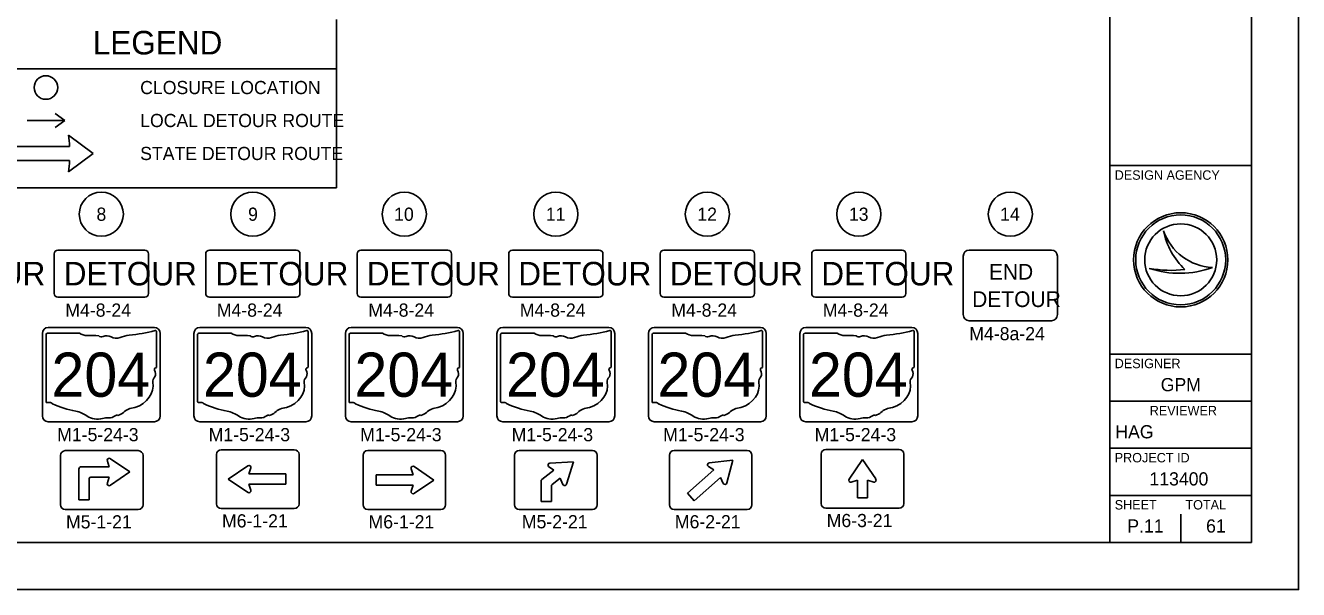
# Model space of a CAD drawing. Extents: x 1880545 to 1948545, y 79309 to 723051.
# Drawn here: x 1921540 to 1948545, y 679051 to 691027 of the extents above; entities that cross this region are included whole.
import ezdxf

# ---------------------------------------------------------------- set-up
doc = ezdxf.new("R2010")
doc.units = 0
for name, color, linetype in [('SH_Border', 7, 'Continuous'), ('SH_Cut_Line', 7, 'Continuous'), ('SH_Data', 7, 'Continuous'), ('SH_Text', 7, 'Continuous'), ('SN_P_Signs', 7, 'Continuous'), ('SN_P_Text', 7, 'Continuous'), ('UT_P_Electric', 7, 'Continuous')]:
    doc.layers.add(name, color=color, linetype=linetype)

msp = doc.modelspace()

# ---------------------------------------------------------------- linework, layer by layer
at = {"layer": 'SH_Border'}
for p, q in [((1944545, 680051), (1944545, 722051)), ((1944545, 688051), (1947545, 688051)), ((1944545, 684051), (1947545, 684051)), ((1944545, 683051), (1947545, 683051)), ((1944545, 682051), (1947545, 682051)), ((1944545, 681051), (1947545, 681051))]:
    msp.add_line(p, q, dxfattribs=at)
msp.add_lwpolyline([(1883545, 722051), (1947545, 722051), (1947545, 680051), (1883545, 680051)], close=True, dxfattribs=at)
at = {"layer": 'SH_Cut_Line'}
msp.add_lwpolyline([(1880545, 679051), (1948545, 679051), (1948545, 723051), (1880545, 723051)], close=True, dxfattribs=at)
at = {"layer": 'SH_Data'}
for p, q in [((1945679, 686670), (1945679, 686670)), ((1946045, 686051), (1946045, 686051)), ((1945379, 685870), (1945379, 685870)), ((1946719, 685888), (1946719, 685888)), ((1946045, 680051), (1946045, 680651)), ((1945295, 680401), (1945295, 680401))]:
    msp.add_line(p, q, dxfattribs=at)
for radius in [1000, 954, 954, 764]:
    msp.add_circle((1946045, 686051), radius, dxfattribs=at)
for centre, radius, start, end in [((1946776, 687046), 1160, 198.9257, 198.9319), ((1947238, 686991), 1591, 191.6379, 191.6421), ((1946776, 687046), 1160, 198.9319, 267.1657), ((1947238, 686991), 1591, 191.6421, 226.0947), ((1946023, 687791), 2026, 251.4576, 290.0832), ((1945841, 688360), 2532, 259.4964, 259.4995), ((1946023, 687791), 2026, 251.4527, 251.4576), ((1945841, 688360), 2532, 259.4995, 276.6672)]:
    msp.add_arc(centre, radius, start, end, dxfattribs=at)
at = {"layer": 'SH_Text'}
for p, q in [((1928141, 691152), (1928141, 687581)), ((1920641, 690105), (1928141, 690105)), ((1921573, 689009), (1921973, 689009)), ((1921973, 689009), (1922373, 689009)), ((1922373, 689009), (1922173, 689159)), ((1922373, 689009), (1922173, 688859)), ((1922453, 688700), (1922973, 688309)), ((1920973, 688459), (1922473, 688459)), ((1922473, 688159), (1920973, 688159)), ((1922973, 688309), (1922453, 687919)), ((1920641, 687581), (1928141, 687581))]:
    msp.add_line(p, q, dxfattribs=at)
for centre in [(1923149, 687020), (1926363, 687020), (1929576, 687020), (1932790, 687020), (1936004, 687020), (1939217, 687020), (1942431, 687020)]:
    msp.add_circle(centre, 468, dxfattribs=at)
for centre, start, end in [((1920973, 688459), 0, 9.2166), ((1920973, 688159), 350.7834, 360)]:
    msp.add_arc(centre, 1500, start, end, dxfattribs=at)
at = {"layer": 'SN_P_Signs'}
for p, q in [((1921977, 684467), (1921977, 683044)), ((1922686, 684491), (1922000, 684491)), ((1924321, 683782), (1924321, 684526)), ((1925191, 684467), (1925191, 683044)), ((1925900, 684491), (1925214, 684491)), ((1927534, 683782), (1927534, 684526)), ((1928404, 684467), (1928404, 683044)), ((1929114, 684491), (1928427, 684491)), ((1930748, 683782), (1930748, 684526)), ((1931618, 684467), (1931618, 683044)), ((1932328, 684491), (1931641, 684491)), ((1933962, 683782), (1933962, 684526)), ((1934832, 684467), (1934832, 683044)), ((1935541, 684491), (1934855, 684491)), ((1937175, 683782), (1937175, 684526)), ((1938045, 684467), (1938045, 683044)), ((1938755, 684491), (1938069, 684491)), ((1940389, 683782), (1940389, 684526)), ((1924320, 683782), (1924321, 683782)), ((1927534, 683782), (1927534, 683782)), ((1930748, 683782), (1930748, 683782)), ((1933962, 683782), (1933962, 683782)), ((1937175, 683782), (1937175, 683782)), ((1940389, 683782), (1940389, 683782))]:
    msp.add_line(p, q, dxfattribs=at)
for points in [[(1922024, 684614), (1924274, 684614)], [(1925238, 684614), (1927488, 684614)], [(1928451, 684614), (1930701, 684614)], [(1931665, 684614), (1933915, 684614)], [(1934879, 684614), (1937129, 684614)], [(1938092, 684614), (1940342, 684614)], [(1921899, 682739), (1921899, 684489)], [(1924399, 684489), (1924399, 682739)], [(1925113, 682739), (1925113, 684489)], [(1927613, 684489), (1927613, 682739)], [(1928326, 682739), (1928326, 684489)], [(1930826, 684489), (1930826, 682739)], [(1931540, 682739), (1931540, 684489)], [(1934040, 684489), (1934040, 682739)], [(1934754, 682739), (1934754, 684489)], [(1937254, 684489), (1937254, 682739)], [(1937967, 682739), (1937967, 684489)], [(1940467, 684489), (1940467, 682739)], [(1924274, 682614), (1922024, 682614)], [(1927488, 682614), (1925238, 682614)], [(1930701, 682614), (1928451, 682614)], [(1933915, 682614), (1931665, 682614)], [(1937129, 682614), (1934879, 682614)], [(1940342, 682614), (1938092, 682614)]]:
    msp.add_lwpolyline(points, dxfattribs=at)
for centre, start, end in [((1922024, 684489), 90, 180), ((1924274, 684489), 0, 90), ((1925238, 684489), 90, 180), ((1927488, 684489), 0, 90), ((1928451, 684489), 90, 180), ((1930701, 684489), 0, 90), ((1931665, 684489), 90, 180), ((1933915, 684489), 0, 90), ((1934879, 684489), 90, 180), ((1937129, 684489), 0, 90), ((1938092, 684489), 90, 180), ((1940342, 684489), 0, 90), ((1922024, 682739), 180, 270), ((1924274, 682739), 270, 0), ((1925238, 682739), 180, 270), ((1927488, 682739), 270, 0), ((1928451, 682739), 180, 270), ((1930701, 682739), 270, 0), ((1931665, 682739), 180, 270), ((1933915, 682739), 270, 0), ((1934879, 682739), 180, 270), ((1937129, 682739), 270, 0), ((1938092, 682739), 180, 270), ((1940342, 682739), 270, 0)]:
    msp.add_arc(centre, 125, start, end, dxfattribs=at)
for centre, major_axis, start_param, end_param in [((1922004, 684470), (27.2, 0), 1.712693, 3.28349), ((1922850, 684656), (263, 0), 4.042523, 4.731795), ((1922937, 683692), (945, 0), 1.404758, 1.657858), ((1923152, 684477), (76, 0), 3.836095, 5.185415), ((1923263, 684313), (158, 0), 0.950623, 2.079405), ((1923467, 684538), (190, 0), 4.081561, 5.145723), ((1923803, 684056), (500, 0), 1.699011, 2.107814), ((1923486, 686431), (2485, 0), 4.814394, 5.042369), ((1924295, 684529), (26.1, 0), 6.141152, 7.989035), ((1925218, 684470), (27.2, 0), 1.712693, 3.28349), ((1926064, 684656), (263, 0), 4.042523, 4.731795), ((1926151, 683692), (945, 0), 1.404758, 1.657858), ((1926366, 684477), (76, 0), 3.836095, 5.185415), ((1926477, 684313), (158, 0), 0.950623, 2.079405), ((1926681, 684538), (190, 0), 4.081561, 5.145723), ((1927017, 684056), (500, 0), 1.699011, 2.107814), ((1926700, 686431), (2485, 0), 4.814394, 5.042369), ((1927508, 684529), (26.1, 0), 6.141152, 7.989035), ((1928431, 684470), (27.2, 0), 1.712693, 3.28349), ((1929277, 684656), (263, 0), 4.042523, 4.731795), ((1929365, 683692), (945, 0), 1.404758, 1.657858), ((1929579, 684477), (76, 0), 3.836095, 5.185415), ((1929691, 684313), (158, 0), 0.950623, 2.079405), ((1929895, 684538), (190, 0), 4.081561, 5.145723), ((1930230, 684056), (500, 0), 1.699011, 2.107814), ((1929913, 686431), (2485, 0), 4.814394, 5.042369), ((1930722, 684529), (26.1, 0), 6.141152, 7.989035), ((1931645, 684470), (27.2, 0), 1.712693, 3.28349), ((1932491, 684656), (263, 0), 4.042523, 4.731795), ((1932578, 683692), (945, 0), 1.404758, 1.657858), ((1932793, 684477), (76, 0), 3.836095, 5.185415), ((1932904, 684313), (158, 0), 0.950623, 2.079405), ((1933108, 684538), (190, 0), 4.081561, 5.145723), ((1933444, 684056), (500, 0), 1.699011, 2.107814), ((1933127, 686431), (2485, 0), 4.814394, 5.042369), ((1933936, 684529), (26.1, 0), 6.141152, 7.989035), ((1934859, 684470), (27.2, 0), 1.712693, 3.28349), ((1935705, 684656), (263, 0), 4.042523, 4.731795), ((1935792, 683692), (945, 0), 1.404758, 1.657858), ((1936007, 684477), (76, 0), 3.836095, 5.185415), ((1936118, 684313), (158, 0), 0.950623, 2.079405), ((1936322, 684538), (190, 0), 4.081561, 5.145723), ((1936658, 684056), (500, 0), 1.699011, 2.107814), ((1936341, 686431), (2485, 0), 4.814394, 5.042369), ((1937149, 684529), (26.1, 0), 6.141152, 7.989035), ((1938072, 684470), (27.2, 0), 1.712693, 3.28349), ((1938918, 684656), (263, 0), 4.042523, 4.731795), ((1939006, 683692), (945, 0), 1.404758, 1.657858), ((1939220, 684477), (76, 0), 3.836095, 5.185415), ((1939332, 684313), (158, 0), 0.950623, 2.079405), ((1939536, 684538), (190, 0), 4.081561, 5.145723), ((1939871, 684056), (500, 0), 1.699011, 2.107814), ((1939554, 686431), (2485, 0), 4.814394, 5.042369), ((1940363, 684529), (26.1, 0), 6.141152, 7.989035), ((1924293, 683779), (27.9, 0), 5.05454, 6.418171), ((1927507, 683779), (27.9, 0), 5.05454, 6.418171), ((1930720, 683779), (27.9, 0), 5.05454, 6.418171), ((1933934, 683779), (27.9, 0), 5.05454, 6.418171), ((1937148, 683779), (27.9, 0), 5.05454, 6.418171), ((1940361, 683779), (27.9, 0), 5.05454, 6.418171), ((1924414, 683470), (176, 0), 2.387724, 3.262537), ((1924315, 683727), (40.4, 0), 1.883978, 3.671073), ((1924058, 683633), (242, 0), 5.934695, 6.695948), ((1927628, 683470), (176, 0), 2.387724, 3.262537), ((1927528, 683727), (40.4, 0), 1.883978, 3.671073), ((1927271, 683633), (242, 0), 5.934695, 6.695948), ((1930842, 683470), (176, 0), 2.387724, 3.262537), ((1930742, 683727), (40.4, 0), 1.883978, 3.671073), ((1930485, 683633), (242, 0), 5.934695, 6.695948), ((1934055, 683470), (176, 0), 2.387724, 3.262537), ((1933956, 683727), (40.4, 0), 1.883978, 3.671073), ((1933699, 683633), (242, 0), 5.934695, 6.695948), ((1937269, 683470), (176, 0), 2.387724, 3.262537), ((1937169, 683727), (40.4, 0), 1.883978, 3.671073), ((1936913, 683633), (242, 0), 5.934695, 6.695948), ((1940483, 683470), (176, 0), 2.387724, 3.262537), ((1940383, 683727), (40.4, 0), 1.883978, 3.671073), ((1940126, 683633), (242, 0), 5.934695, 6.695948), ((1923625, 683376), (622, 0), 5.101752, 6.440018), ((1926839, 683376), (622, 0), 5.101752, 6.440018), ((1930052, 683376), (622, 0), 5.101752, 6.440018), ((1933266, 683376), (622, 0), 5.101752, 6.440018), ((1936480, 683376), (622, 0), 5.101752, 6.440018), ((1939694, 683376), (622, 0), 5.101752, 6.440018), ((1922004, 683040), (27.4, 0), 3.00124, 4.508301), ((1922008, 683186), (209, 0), 4.665946, 4.897461), ((1922051, 682961), (75.4, 0), 0.519207, 1.627899), ((1923003, 684240), (1795, 0), 4.195997, 4.488961), ((1925218, 683040), (27.4, 0), 3.00124, 4.508301), ((1925222, 683186), (209, 0), 4.665946, 4.897461), ((1925265, 682961), (75.4, 0), 0.519207, 1.627899), ((1926216, 684240), (1795, 0), 4.195997, 4.488961), ((1928431, 683040), (27.4, 0), 3.00124, 4.508301), ((1928436, 683186), (209, 0), 4.665946, 4.897461), ((1928478, 682961), (75.4, 0), 0.519207, 1.627899), ((1929430, 684240), (1795, 0), 4.195997, 4.488961), ((1931645, 683040), (27.4, 0), 3.00124, 4.508301), ((1931649, 683186), (209, 0), 4.665946, 4.897461), ((1931692, 682961), (75.4, 0), 0.519207, 1.627899), ((1932644, 684240), (1795, 0), 4.195997, 4.488961), ((1934859, 683040), (27.4, 0), 3.00124, 4.508301), ((1934863, 683186), (209, 0), 4.665946, 4.897461), ((1934906, 682961), (75.4, 0), 0.519207, 1.627899), ((1935857, 684240), (1795, 0), 4.195997, 4.488961), ((1938073, 683040), (27.4, 0), 3.00124, 4.508301), ((1938077, 683186), (209, 0), 4.665946, 4.897461), ((1938119, 682961), (75.4, 0), 0.519207, 1.627899), ((1939071, 684240), (1795, 0), 4.195997, 4.488961), ((1922468, 682404), (562, 0), 0.823519, 1.323587), ((1923075, 682954), (356, 0), 4.026481, 4.996735), ((1923281, 682462), (293, 0), 1.495662, 1.94098), ((1923307, 682848), (190, 0), 4.691044, 5.507374), ((1923479, 682710), (53.5, 0), 1.147584, 2.315152), ((1923456, 682906), (201, 0), 4.937069, 5.64225), ((1923887, 682644), (340, 0), 1.647645, 2.488434), ((1925681, 682404), (562, 0), 0.823519, 1.323587), ((1926289, 682954), (356, 0), 4.026481, 4.996735), ((1926495, 682462), (293, 0), 1.495662, 1.94098), ((1926521, 682848), (190, 0), 4.691044, 5.507374), ((1926692, 682710), (53.5, 0), 1.147584, 2.315152), ((1926670, 682906), (201, 0), 4.937069, 5.64225), ((1927101, 682644), (340, 0), 1.647645, 2.488434), ((1928895, 682404), (562, 0), 0.823519, 1.323587), ((1929502, 682954), (356, 0), 4.026481, 4.996735), ((1929708, 682462), (293, 0), 1.495662, 1.94098), ((1929734, 682848), (190, 0), 4.691044, 5.507374), ((1929906, 682710), (53.5, 0), 1.147584, 2.315152), ((1929883, 682906), (201, 0), 4.937069, 5.64225), ((1930315, 682644), (340, 0), 1.647645, 2.488434), ((1932109, 682404), (562, 0), 0.823519, 1.323587), ((1932716, 682954), (356, 0), 4.026481, 4.996735), ((1932922, 682462), (293, 0), 1.495662, 1.94098), ((1932948, 682848), (190, 0), 4.691044, 5.507374), ((1933120, 682710), (53.5, 0), 1.147584, 2.315152), ((1933097, 682906), (201, 0), 4.937069, 5.64225), ((1933528, 682644), (340, 0), 1.647645, 2.488434), ((1935322, 682404), (562, 0), 0.823519, 1.323587), ((1935930, 682954), (356, 0), 4.026481, 4.996735), ((1936136, 682462), (293, 0), 1.495662, 1.94098), ((1936162, 682848), (190, 0), 4.691044, 5.507374), ((1936333, 682710), (53.5, 0), 1.147584, 2.315152), ((1936311, 682906), (201, 0), 4.937069, 5.64225), ((1936742, 682644), (340, 0), 1.647645, 2.488434), ((1938536, 682404), (562, 0), 0.823519, 1.323587), ((1939143, 682954), (356, 0), 4.026481, 4.996735), ((1939349, 682462), (293, 0), 1.495662, 1.94098), ((1939375, 682848), (190, 0), 4.691044, 5.507374), ((1939547, 682710), (53.5, 0), 1.147584, 2.315152), ((1939524, 682906), (201, 0), 4.937069, 5.64225), ((1939956, 682644), (340, 0), 1.647645, 2.488434)]:
    msp.add_ellipse(centre, major_axis=major_axis, ratio=0.8, start_param=start_param, end_param=end_param, dxfattribs=at)
at = {"layer": 'UT_P_Electric'}
for p, q in [((1922284, 681901), (1922284, 680851)), ((1923934, 682001), (1922384, 682001)), ((1924034, 680851), (1924034, 681901)), ((1925593, 681921), (1925593, 680871)), ((1927243, 682021), (1925693, 682021)), ((1927243, 682021), (1927243, 682021)), ((1927343, 680871), (1927343, 681921)), ((1928700, 680852), (1928700, 681902)), ((1928800, 682002), (1930350, 682002)), ((1930450, 681902), (1930450, 680852)), ((1931915, 681902), (1931915, 680852)), ((1933565, 682002), (1932015, 682002)), ((1933665, 680852), (1933665, 681902)), ((1935199, 680852), (1935199, 681902)), ((1935299, 682002), (1936849, 682002)), ((1936949, 681902), (1936949, 680852)), ((1938420, 680878), (1938420, 681928)), ((1938520, 682028), (1940070, 682028)), ((1940170, 681928), (1940170, 680878)), ((1922675, 680954), (1922675, 681610)), ((1922721, 681657), (1923315, 681657)), ((1922721, 681657), (1922721, 681657)), ((1923315, 681657), (1923274, 681797)), ((1923345, 681827), (1923753, 681547)), ((1925843, 681396), (1926257, 681681)), ((1926320, 681634), (1926281, 681506)), ((1929723, 681614), (1929763, 681486)), ((1930200, 681377), (1929787, 681661)), ((1932748, 681588), (1932637, 681664)), ((1932664, 681735), (1933165, 681766)), ((1932664, 681735), (1932664, 681735)), ((1933165, 681766), (1933014, 681287)), ((1936142, 681593), (1936027, 681663)), ((1936044, 681740), (1936543, 681799)), ((1936044, 681740), (1936044, 681740)), ((1936543, 681799), (1936420, 681320)), ((1939011, 681395), (1939295, 681809)), ((1939295, 681809), (1939575, 681401)), ((1922893, 681407), (1922893, 680954)), ((1923315, 681438), (1922925, 681438)), ((1923274, 681297), (1923315, 681438)), ((1923753, 681547), (1923345, 681268)), ((1926251, 681117), (1925843, 681396)), ((1926281, 681506), (1927062, 681506)), ((1927062, 681506), (1927062, 681287)), ((1929763, 681486), (1928982, 681486)), ((1928982, 681486), (1928982, 681267)), ((1929792, 681097), (1930200, 681377)), ((1932478, 680924), (1932478, 681354)), ((1932496, 681391), (1932748, 681588)), ((1932883, 681416), (1932709, 681279)), ((1932933, 681299), (1932883, 681416)), ((1935580, 681100), (1936142, 681593)), ((1936286, 681429), (1935724, 680936)), ((1936341, 681306), (1936286, 681428)), ((1939186, 681372), (1939057, 681332)), ((1939186, 680997), (1939186, 681372)), ((1939533, 681332), (1939404, 681372)), ((1939404, 681372), (1939404, 680997)), ((1927062, 681287), (1926281, 681287)), ((1926281, 681287), (1926320, 681159)), ((1928982, 681267), (1929763, 681267)), ((1929763, 681267), (1929723, 681139)), ((1932696, 681254), (1932696, 680924)), ((1935724, 680936), (1935580, 681100)), ((1922893, 680954), (1922675, 680954)), ((1932696, 680924), (1932478, 680924)), ((1939404, 680997), (1939186, 680997)), ((1922384, 680751), (1923934, 680751)), ((1925693, 680771), (1927243, 680771)), ((1930350, 680752), (1928800, 680752)), ((1932015, 680752), (1933565, 680752)), ((1936849, 680752), (1935299, 680752)), ((1940070, 680778), (1938520, 680778))]:
    msp.add_line(p, q, dxfattribs=at)
for points in [[(1924069, 686258), (1922229, 686258)], [(1927283, 686258), (1925443, 686258)], [(1930496, 686258), (1928656, 686258)], [(1933710, 686258), (1931870, 686258)], [(1936924, 686258), (1935084, 686258)], [(1940137, 686258), (1938297, 686258)], [(1943301, 686258), (1941561, 686258)], [(1922149, 686178), (1922149, 685338)], [(1924149, 685338), (1924149, 686178)], [(1925363, 686178), (1925363, 685338)], [(1927363, 685338), (1927363, 686178)], [(1928576, 686178), (1928576, 685338)], [(1930576, 685338), (1930576, 686178)], [(1931790, 686178), (1931790, 685338)], [(1933790, 685338), (1933790, 686178)], [(1935004, 686178), (1935004, 685338)], [(1937004, 685338), (1937004, 686178)], [(1938217, 686178), (1938217, 685338)], [(1940217, 685338), (1940217, 686178)], [(1941431, 686128), (1941431, 684888)], [(1943431, 684888), (1943431, 686128)], [(1922229, 685258), (1924069, 685258)], [(1925443, 685258), (1927283, 685258)], [(1928656, 685258), (1930496, 685258)], [(1931870, 685258), (1933710, 685258)], [(1935084, 685258), (1936924, 685258)], [(1938297, 685258), (1940137, 685258)], [(1941561, 684758), (1943301, 684758)]]:
    msp.add_lwpolyline(points, dxfattribs=at)
msp.add_circle((1921973, 689709), 250, dxfattribs=at)
for centre, radius, start, end in [((1922229, 686178), 80, 90, 180), ((1924069, 686178), 80, 0, 90), ((1925443, 686178), 80, 90, 180), ((1927283, 686178), 80, 0, 90), ((1928656, 686178), 80, 90, 180), ((1930496, 686178), 80, 0, 90), ((1931870, 686178), 80, 90, 180), ((1933710, 686178), 80, 0, 90), ((1935084, 686178), 80, 90, 180), ((1936924, 686178), 80, 0, 90), ((1938297, 686178), 80, 90, 180), ((1940137, 686178), 80, 0, 90), ((1941561, 686128), 130, 90, 180), ((1943301, 686128), 130, 0, 90), ((1922229, 685338), 80, 180, 270), ((1924069, 685338), 80, 270, 0), ((1925443, 685338), 80, 180, 270), ((1927283, 685338), 80, 270, 0), ((1928656, 685338), 80, 180, 270), ((1930496, 685338), 80, 270, 0), ((1931870, 685338), 80, 180, 270), ((1933710, 685338), 80, 270, 0), ((1935084, 685338), 80, 180, 270), ((1936924, 685338), 80, 270, 0), ((1938297, 685338), 80, 180, 270), ((1940137, 685338), 80, 270, 0), ((1941561, 684888), 130, 180, 270), ((1943301, 684888), 130, 270, 0), ((1922384, 681900), 100, 90, 180), ((1923934, 681900), 100, 0, 90), ((1925693, 681921), 100, 90, 180), ((1927243, 681921), 100, 0, 90), ((1928801, 681902), 100, 90, 180), ((1930351, 681902), 100, 0, 90), ((1932015, 681902), 100, 90, 180), ((1933565, 681902), 100, 0, 90), ((1935299, 681902), 100, 90, 180), ((1936849, 681902), 100, 0, 90), ((1938520, 681928), 100, 90, 180), ((1940070, 681928), 100, 0, 90), ((1922722, 681610), 46.9, 90, 180), ((1923315, 681797), 41.7, 45.0001, 179.9983), ((1926281, 681646), 41.7, 342.7954, 124.5888), ((1929763, 681627), 41.7, 55.4112, 197.2046), ((1932666, 681693), 41.7, 93.5999, 225.0001), ((1936049, 681699), 41.7, 96.6699, 238.4633), ((1922925, 681407), 31.2, 90, 180), ((1932524, 681354), 46.8, 127.7857, 180), ((1939045, 681372), 41.7, 145.4112, 287.2046), ((1939545, 681372), 41.7, 252.7954, 45.0096), ((1923315, 681297), 41.7, 179.9983, 314.9999), ((1926281, 681146), 41.7, 224.9904, 17.2046), ((1929763, 681127), 41.7, 162.7954, 315.0096), ((1932728, 681254), 31.2, 127.3494, 180), ((1932974, 681299), 41.7, 180.0509, 342.5804), ((1936379, 681323), 41.7, 204.0541, 356.2683), ((1922384, 680850), 100, 180, 270), ((1923934, 680850), 100, 270, 0), ((1925693, 680871), 100, 180, 270), ((1927243, 680871), 100, 270, 0), ((1928801, 680852), 100, 180, 270), ((1930351, 680852), 100, 270, 360), ((1932015, 680852), 100, 180, 270), ((1933565, 680852), 100, 270, 360), ((1935299, 680852), 100, 180, 270), ((1936849, 680852), 100, 270, 0), ((1938520, 680878), 100, 180, 270), ((1940070, 680878), 100, 270, 0)]:
    msp.add_arc(centre, radius, start, end, dxfattribs=at)

# ---------------------------------------------------------------- texts
at = {"layer": 'SH_Data'}
for s, height, p in [('DESIGN AGENCY', 200, (1944645, 687751)), ('DESIGNER', 200, (1944645, 683751)), ('GPM', 280, (1945621, 683261)), ('REVIEWER', 200, (1945388, 682751)), ('HAG', 280, (1944658, 682261)), ('PROJECT ID', 200, (1944645, 681751)), ('113400', 280, (1945382, 681261)), ('SHEET', 200, (1944645, 680751)), ('TOTAL', 200, (1946145, 680751)), ('P.11', 280, (1944913, 680261)), ('61', 280, (1946583, 680261))]:
    msp.add_text(s, height=height, dxfattribs=at).set_placement(p)
at = {"layer": 'SH_Text'}
for s, height, p in [('LEGEND', 500, (1922967, 690411)), ('CLOSURE LOCATION', 280, (1923973, 689569)), ('LOCAL DETOUR ROUTE', 280, (1923973, 688869)), ('STATE DETOUR ROUTE', 280, (1923973, 688169)), ('8', 280, (1923046, 686880)), ('9', 280, (1926262, 686880)), ('10', 280, (1929360, 686880)), ('11', 280, (1932578, 686880)), ('12', 280, (1935792, 686880)), ('13', 280, (1939007, 686880)), ('14', 280, (1942214, 686880))]:
    msp.add_text(s, height=height, dxfattribs=at).set_placement(p)
at = {"layer": 'SN_P_Signs'}
for p in [(1922092, 683144), (1925305, 683144), (1928519, 683144), (1931733, 683144), (1934947, 683144), (1938160, 683144)]:
    msp.add_text('204', height=937.5, dxfattribs=at).set_placement(p)
at = {"layer": 'SN_P_Text'}
for s, p in [('M4-8-24', (1922385, 684844)), ('M4-8-24', (1925598, 684844)), ('M4-8-24', (1928812, 684844)), ('M4-8-24', (1932026, 684844)), ('M4-8-24', (1935239, 684844)), ('M4-8-24', (1938453, 684844)), ('M4-8a-24', (1941561, 684344)), ('M1-5-24-3', (1922212, 682200)), ('M1-5-24-3', (1925426, 682200)), ('M1-5-24-3', (1928640, 682200)), ('M1-5-24-3', (1931853, 682200)), ('M1-5-24-3', (1935067, 682200)), ('M1-5-24-3', (1938281, 682200)), ('M5-1-21', (1922400, 680349)), ('M6-1-21', (1925709, 680370)), ('M6-1-21', (1928817, 680350)), ('M5-2-21', (1932069, 680351)), ('M6-2-21', (1935315, 680351)), ('M6-3-21', (1938536, 680377))]:
    msp.add_text(s, height=280, dxfattribs=at).set_placement(p)
at = {"layer": 'UT_P_Electric'}
for s, height, p in [('DETOUR', 500, (1919138, 685508)), ('DETOUR', 500, (1922352, 685508)), ('DETOUR', 500, (1925566, 685508)), ('DETOUR', 500, (1928780, 685508)), ('DETOUR', 500, (1931993, 685508)), ('DETOUR', 500, (1935207, 685508)), ('DETOUR', 500, (1938421, 685508)), ('END', 333.3, (1941975, 685631)), ('DETOUR', 333.3, (1941621, 685049))]:
    msp.add_text(s, height=height, dxfattribs=at).set_placement(p)

doc.saveas('drawing.dxf')
